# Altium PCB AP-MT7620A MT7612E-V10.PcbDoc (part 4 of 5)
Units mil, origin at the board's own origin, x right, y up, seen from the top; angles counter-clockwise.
Board outline 4645.67 x 3740.16 mil, 4 copper layers (Top, Inner Layer 2, Inner Layer 3, Bottom), stack 35.4 mil thick; 603 components, 409 nets, 1850 pads, 2004 vias.
Unrouted connection lines stored in the file: 90.
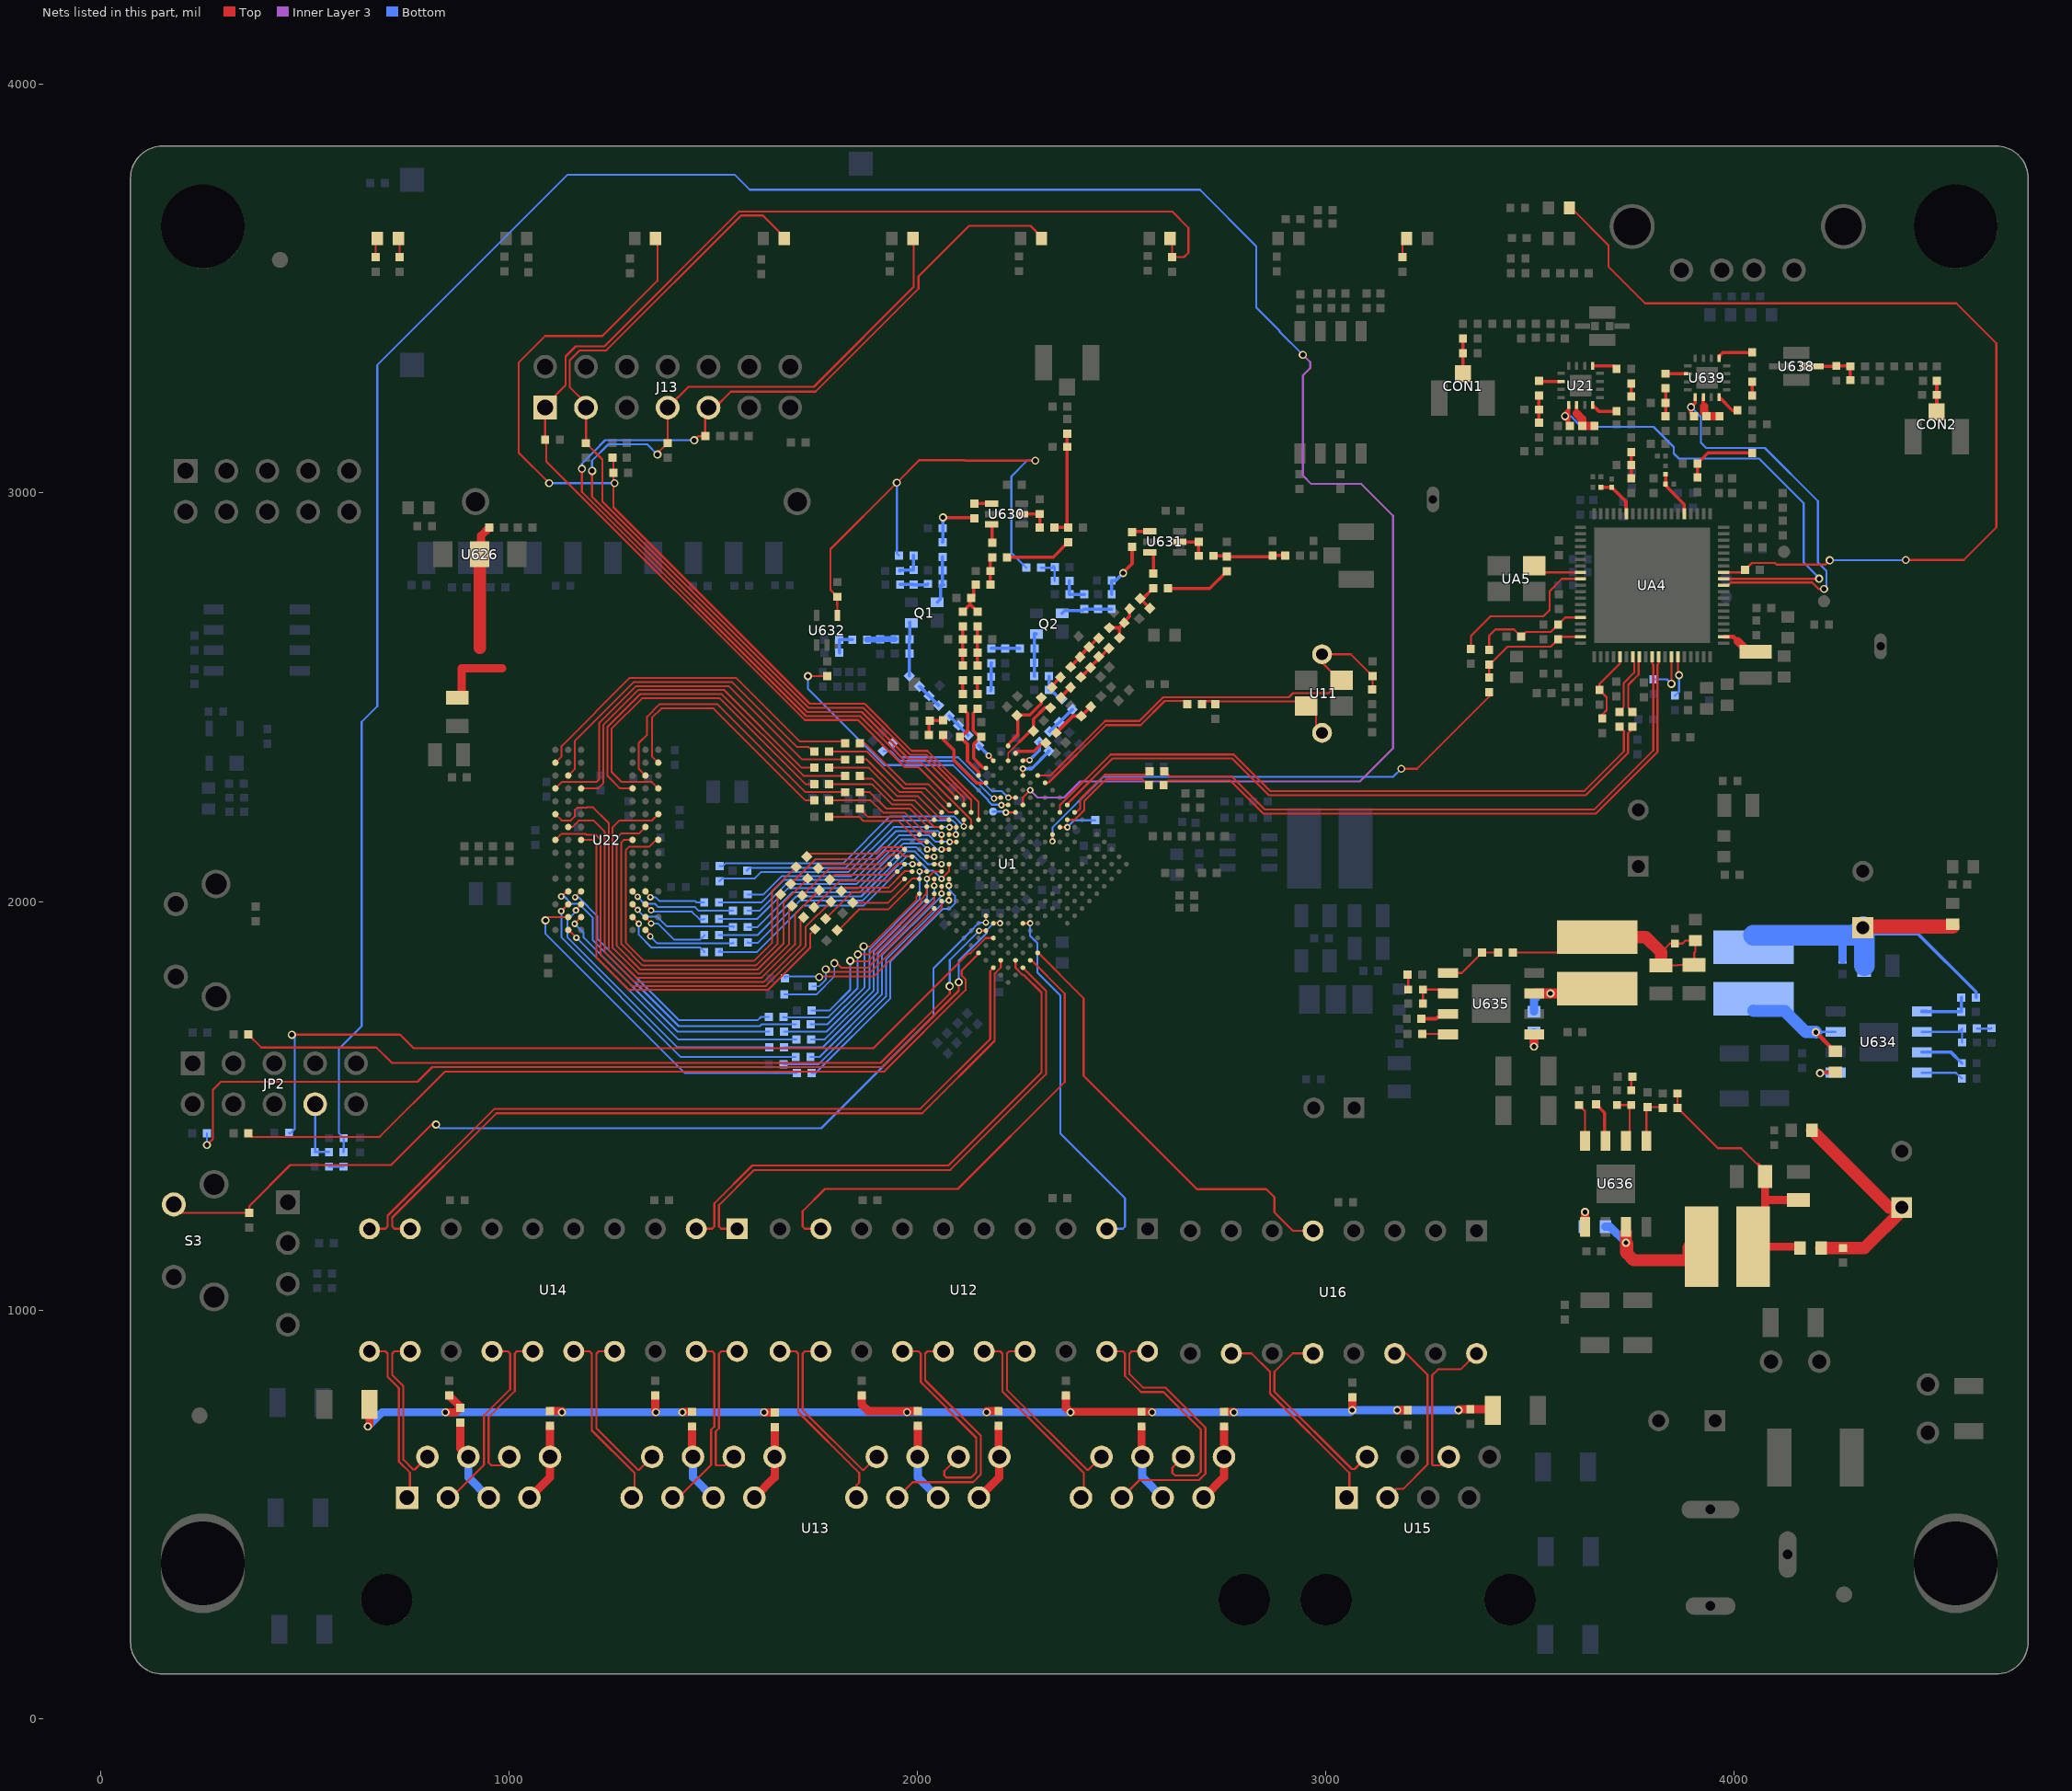
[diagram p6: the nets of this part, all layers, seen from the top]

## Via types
v1: diameter 20, hole 12, Top to Bottom, 1824 vias
v2: diameter 16, hole 8, Top to Bottom, 180 vias

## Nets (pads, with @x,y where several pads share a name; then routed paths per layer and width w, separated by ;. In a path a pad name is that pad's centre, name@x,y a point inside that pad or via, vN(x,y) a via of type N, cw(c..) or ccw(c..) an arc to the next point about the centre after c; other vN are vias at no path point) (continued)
LANP0_C1: R120.1 U13.4 U13.5 | length 213
  Top w20: R120.1@881,725 881,661 U13.4@901,641
  Bottom w20: U13.4@901,641 901,591 U13.5@951,541
LANP0_C2: R119.1 U13.7 U13.8 | length 196.7
  Top w20: U13.7@1051,541 1101,591 U13.8@1101,641 R119.1@1101,717
LANP1_C1: R117.1 U13.12 U13.13 | length 196.7
  Top w20: R117.1@1449,715 1449,641 U13.12@1451,641
  Bottom w20: U13.12@1451,641 1451,591 U13.13@1501,541
LANP1_C2: R116.1 U13.15 U13.16 | length 192.7
  Top w20: U13.15@1601,541 1651,591 U13.16@1651,641 R116.1@1651,713
LANP2_C1: R114.1 U13.20 U13.21 | length 196.7
  Top w20: U13.20@2001,641 R114.1@2001,717
  Bottom w20: U13.20@2001,641 2001,591 U13.21@2051,541
LANP2_C2: R113.1 U13.23 U13.24 | length 198.7
  Top w20: U13.23@2151,541 2201,591 U13.24@2201,641 2199,641 R113.1@2199,717
LANP3_C1: R111.1 U13.28 U13.29 | length 196.7
  Top w20: R111.1@2549,715 2549,641 U13.28@2551,641
  Bottom w20: U13.28@2551,641 2551,591 U13.29@2601,541
LANP3_C2: R110.1 U13.31 U13.32 | length 194.7
  Top w20: U13.31@2701,541 2751,591 U13.32@2751,641 R110.1@2751,715
LED_7612_5G: D17.2 RA10.2 UA4.50 | length 2380.6
  Top w5: D17.2@3596.59,3698 3600.53,3698 3692,3606.53 3692,3554 3782,3464 4544,3464 4642,3366 4642,2916 4562,2836 v1(4420,2836) ; UA4.50@3974.2,2805.5 4020.38,2805.5 RA10.2@4026.88,2812 4043.38,2828.5 4099.76,2828.5 4103.76,2824.5 4223.4,2824.5 v1(4233.99,2835.09)
  Bottom w5: v1(4233.99,2835.09) 4419.09,2835.09 v1(4420,2836)
LINK0: C845.1 D12.2 R478.2 U1.H4 | length 2376.8
  Top w5: v1(1099,3024) 1024,3099 1024,3319 1089,3384 1229,3384 1364,3519 1364,3618.37 1363.37,3619 D12.2@1363.37,3622.78 ; R478.2@1254,3086 1256,3086 C845.1@1256,3049 v1@1256,3027 ; v1(1259,3024) v1@1256,3027 ; U1.H4@2150.12,2200.07 2150.12,2243.61 2024.73,2369 1986.5,2369 1871.5,2484 1736.69,2484 1256,2964.69 v1@1256,3027
  Bottom w5: v1(1099,3024) v1(1259,3024)
LINK1: D11.2 J13.3 R476.2 U1.H3 | length 2314.1
  Top w5: D11.2@1678.33,3622.78 1622.11,3679 1569,3679 1239,3349 1174,3349 1149,3324 1149,3259.04 1189,3219.04 J13.3@1189,3209 R476.2@1189,3122 1229,3082 1229,2978.92 1733.92,2474 1868,2474 1983,2359 2022,2359 2132.02,2248.98 U1.H3@2132.02,2218.17
LINK2: D10.2 J13.7 R474.2 U1.H2 | length 2481.2
  Top w5: v1(1204,3054) 1204,2990.84 1730.84,2464 1864,2464 1979,2349 2019,2349 2113.93,2254.07 U1.H2@2113.93,2236.26 ; v1(1364,3094) 1364,3097 R474.2@1389,3122 J13.7@1389,3209 1440,3260 1747,3260 1991,3504 1991,3620.49 1993.29,3622.78 D10.2@1989.35,3622.78
  Bottom w5: v1(1204,3054) 1204,3079 1244,3119 1339,3119 v1(1364,3094)
LINK3: D9.2 J13.9 R473.2 U1.H1 | length 2738.6
  Top w5: v1(1179,3059) 1179,3002.72 1727.72,2454 1860,2454 1975,2339 2011.19,2339 U1.H1@2095.83,2254.36 ; v1(1454,3129) 1464,3139 R473.2@1481,3139 1481,3204 1484,3204 J13.9@1489,3209 1505,3209 1544,3248 1751,3248 2003,3500 2003,3530 2127,3654 2277.03,3654 2308.25,3622.78 D9.2@2304.31,3622.78
  Bottom w5: v1(1179,3059) 1179,3071 1236,3129 v1(1454,3129)
LINK4: C846.1 D8.2 J13.1 R477.2 U1.J4 | length 3544.5
  Top w5: U1.J4@2132.02,2181.98 2132.02,2200 2003.02,2329 1970,2329 1855,2444 1724.98,2444 1092,3076.98 1092,3127 R477.2@1089,3130 J13.1@1089,3209 1093.55,3213.55 1093.55,3218.55 1139,3264 1139,3334 1164,3359 1234,3359 1564,3689 2624,3689 2664,3649 2664,3588 2653,3577 C846.1@2624,3577 2624,3622 2623.22,3622.78 D8.2@2619.28,3622.78
LNA2G5G_PE0: C160.2 U21.5 UA4.49 | length 1210.9
  Top w5: UA4.49@3974.2,2789.75 3974.2,2790 v1(4208,2790)
  Top w8: U21.5@3594.47,3215.26 3594.47,3204 ; C160.2@3598,3164 3594.47,3164 3594.47,3176 ; 3594.47,3176 3594.47,3204 ; 3594.47,3176 3591.16,3176 3586,3181.16 v1(3586,3188) 3586,3195.53 3594.47,3204
  Bottom w5: v1(3586,3188) 3600,3188 3626,3162 3802.45,3162 3852,3112.45 3852,3096.59 3864.59,3084 4061,3084 4170,2975 4170,2830 4210,2790 v1(4208,2790)
LNA2G5G_PE1: C162.2 U639.5 UA4.48 | length 977.7
  Top w5: UA4.48@3974.2,2774 3986,2774 3992.75,2780.75 4190.76,2780.75 4206.51,2765 v1(4220,2765)
  Top w8: v1(3894.42,3210.04) 3904.47,3220.09 U639.5@3904.47,3234.26
  Top w10: v1(3894.42,3210.04) 3894.42,3196.52 3902,3188.94 C162.2@3902,3188
  Bottom w5: v1(3894.42,3210.04) 3918.5,3185.96 3918.5,3122.87 3931.51,3109.87 4075.13,3109.87 4205,2980 4205,2830 4226,2809 4226,2771 v1(4220,2765)
LNA_PE_G0: R918.2 R928.2 R954.2 U632.4 | length 1254.4
  Top w5: U632.4@1804.59,2700.28 1804.59,2724.73 1804,2725.32 R954.2@1804,2746 1787.5,2762.5 1787.5,2862.5 v1(1950,3025) 2005,3080 2115.25,3080 2116.25,3079 v1(2289,3079)
  Bottom w5: v1(1950,3025) 1950,2852 R918.2@1955,2847 ; R928.2@2267,2817 2230.5,2853.5 2230.5,3040.5 2269,3079 v1(2289,3079)
LNA_RX0_IN: C996.1 C1002.1 C1006.2 | length 142.3
  Top w8: v1(2504,2804) 2504,2805 2526,2827 C1006.2@2526,2868
  Bottom w8: C1002.1@2476,2752 C996.1@2476,2785.5 2485.5,2785.5 v1(2504,2804)
LNA_RX1_IN: C984.1 C989.1 C1053.1 | length 138.2
  Top w8: v1(2063,2940) 2137.5,2940 C1053.1@2139.5,2938
  Bottom w8: C984.1@2062,2879.5 2062.5,2880 C989.1@2062.5,2913.5 2063,2914 v1(2063,2940)
LNA_V0: C1001.2 L641.1 R924.1 | length 69.7
  Bottom w8: R924.1@2181.5,2619.5 C1001.2@2215,2619.5 2250.5,2619.5 L641.1@2251,2619
LNAO0: C1003.2 C1005.2 L641.2 Q2.3 | length 110.2
  Bottom w8: C1003.2@2286.5,2551.5 C1005.2@2286.5,2584 2287,2584 L641.2@2287,2619 2287,2656 2289.91,2656 Q2.3@2291.5,2654.41
LNAO1: C980.2 C982.2 L638.2 Q1.3 | length 133.3
  Bottom w8: C980.2@1980.27,2552.23 1980.27,2606.27 C982.2@1981,2607 L638.2@1981,2642 1981.78,2642.78 1981.78,2683.8 Q1.3@1981,2683.03
MA0: R65.1 U1.L4 | length 656.6
  Top w5: v2(2079.5,2146) 2079.71,2145.79 U1.L4@2095.83,2145.79
  Bottom w4.5: R65.1@1514.5,1997.5 1618.5,1997.5 1673.5,2052.5 1845.5,2052.5 1955.5,2162.5 2028.5,2162.5 2045,2146 v2(2079.5,2146)
MA0+: U13.1 U14.11 | length 424.7
  Top w5: U14.11@659,899 698,899 703.5,893.5 703.5,836.72 731,809.22 731,629.22 757.97,602.25 757.97,547.97 U13.1@751,541
MA0-: U13.2 U14.12 | length 399.6
  Top w5: U14.12@759,899 720,899 714.5,893.5 714.5,841.28 742,813.78 742,633.78 765.75,610.03 770.03,610.03 U13.2@801,641
MA1: R67.1 U1.T5 | length 548.5
  Top w4.5: v1(1854.5,1870.5) 1881,1870.5 2009.5,1999 2009.5,2005.5 2022.5,2018.5 2022.5,2036.26 U1.T5@2023.45,2037.21
  Bottom w4.5: R67.1@1672.5,1717.5 1671.5,1717.5 1672.5,1716.5 1782.5,1716.5 1854.5,1788.5 v1(1854.5,1870.5)
MA1+: U13.9 U14.16 | length 445.4
  Top w5: U14.16@1159,899 1198,899 1203.5,893.5 1203.5,705.72 1307.97,601.25 1307.97,555.97 1301,549 U13.9@1301,541
MA1-: U13.10 U14.17 | length 421.7
  Top w5: U14.17@1259,899 1220,899 1214.5,893.5 1214.5,710.28 1315.75,609.03 1319.03,609.03 U13.10@1351,641
MA2: R69.1 U1.M4 | length 576.2
  Top w5: v2(2059.5,2127.5) 2059.69,2127.69 U1.M4@2077.74,2127.69
  Bottom w4.5: R69.1@1584.5,1977.5 1613.5,1977.5 1678.5,2042.5 1851.1,2042.5 1961.1,2152.5 2023.5,2152.5 2048.5,2127.5 v2(2059.5,2127.5)
MA2+: U12.11 U13.17 | length 464.1
  Top w5: U12.11@1664,899 1703,899 1708.5,893.5 1708.5,750.72 1857.97,601.25 1857.97,578.03 1851,571.06 U13.17@1851,541
MA2-: U12.12 U13.18 | length 440.3
  Top w5: U12.12@1764,899 1725,899 1719.5,893.5 1719.5,755.28 1865.75,609.03 1869.03,609.03 U13.18@1901,641
MA3: R71.1 U1.R6 | length 563.6
  Top w4.5: v2(2059.5,2019.5) 2059.64,2019.64 U1.R6@2059.64,2037.21
  Bottom w4.5: R71.1@1738.5,1619.5 1760.5,1619.5 1913.5,1772.5 1913.5,1867.5 2059.5,2013.5 v2(2059.5,2019.5)
MA3+: U12.16 U13.25 | length 484.8
  Top w5: U12.16@2164,899 2203,899 2208.5,893.5 2208.5,800.72 2407.97,601.25 2407.97,547.97 U13.25@2401,541
MA3-: U12.17 U13.26 | length 461
  Top w5: U12.17@2264,899 2225,899 2219.5,893.5 2219.5,805.28 2415.75,609.03 2419.03,609.03 U13.26@2451,641
MA4: R73.1 U1.N3 | length 610
  Top w5: v2(2024.5,2127.5) 2024.69,2127.69 U1.N3@2041.55,2127.69
  Bottom w4.5: R73.1@1514.5,1957.5 1608.5,1957.5 1683.5,2032.5 1855.5,2032.5 1965.5,2142.5 2009.5,2142.5 v2(2024.5,2127.5)
MA4+: U15.1 U16.10 | length 504.5
  Top w5: U16.10@2769,894 2818.41,894 2863.5,848.91 2863.5,795.72 3057.97,601.25 3057.97,547.97 U15.1@3051,541
MA4-: U15.2 U16.12 | length 479.3
  Top w5: U16.12@2969,894 2919.59,894 2874.5,848.91 2874.5,800.28 3063.98,610.8 3070.8,610.8 U15.2@3101,641
MA5: R75.1 U1.R5 | length 620.5
  Top w4.5: v2(2041.5,2038.5) v2(2041.5,2038.5) U1.R5@2041.55,2055.31
  Bottom w4.5: R75.1@1673.5,1643.5 1769.5,1643.5 1903.5,1777.5 1903.5,1872.5 2041.5,2010.5 v2(2041.5,2038.5)
MA6: R77.1 U1.P3 | length 565.4
  Top w5: U1.P3@2023.45,2109.6 2041.4,2109.6 v2(2041.5,2109.5)
  Bottom w4.5: R77.1@1584.5,1937.5 1608.76,1937.5 1693.76,2022.5 1859.5,2022.5 1969.5,2132.5 1998.5,2132.5 2021.5,2109.5 v2(2041.5,2109.5)
MA7: R79.1 U1.P6 | length 641.7
  Top w4.5: v2(2077.5,2039) 2077.74,2039.24 U1.P6@2077.74,2055.31
  Bottom w4.5: R79.1@1741.5,1580.5 1751.5,1580.5 1933.5,1762.5 1933.5,1852.5 2063.5,1982.5 2079.5,1982.5 2092.5,1995.5 2092.5,2014.5 2077.5,2029.5 v2(2077.5,2039)
MA8: R81.1 U1.P4 | length 660.7
  Top w5: U1.P4@2041.55,2091.5 v2(2059.5,2091.5)
  Bottom w4.5: R81.1@1514.5,1917.5 1608.5,1917.5 1703.5,2012.5 1863,2012.5 1973,2122.5 1994.5,2122.5 2025.5,2091.5 v2(2059.5,2091.5)
MA9: R83.1 U1.R4 | length 608.1
  Top w4.5: v2(2005.5,2073.5) 2005.6,2073.4 U1.R4@2023.45,2073.4
  Bottom w4.5: R83.1@1673.5,1681.5 1777.5,1681.5 1883.5,1787.5 1883.5,1882.5 2005.5,2005.5 v2(2005.5,2073.5)
MA10: R85.1 U1.U5 | length 466
  Top w4.5: v1(1869,1890) 1885,1890 1997.62,2002.62 1997.62,2011.38 U1.U5@2005.36,2019.12
  Bottom w4.5: R85.1@1739.5,1699.5 1780.5,1699.5 1871,1790 1871,1890 v1(1869,1890)
MA11: R87.1 U1.R3 | length 589.5
  Top w5: v2(1988.5,2091.5) U1.R3@2005.36,2091.5
  Bottom w4.5: R87.1@1514.5,1876.5 1513.5,1876.5 1518.5,1881.5 1518.5,1876.5 1607.5,1876.5 1721.25,1990.25 1868.75,1990.25 1970.65,2092.15 1987.85,2092.15 v2(1988.5,2091.5)
MA12: R89.1 U1.P5 | length 572.8
  Top w4.5: v2(2023.5,2055.5) 2041.4,2073.4 U1.P5@2059.64,2073.4
  Bottom w4.5: R89.1@1740.5,1662.5 1773.5,1662.5 1893.5,1782.5 1893.5,1877.5 2023.5,2008.5 v2(2023.5,2055.5)
MA13: R826.1 U1.N5 | length 630.7
  Top w4.5: v2(2059.5,2055.5) 2077.5,2073.5 2077.5,2091.26 U1.N5@2077.74,2091.5
  Bottom w4.5: R826.1@1585.5,1899.5 1584.5,1899.5 1584.5,1898.5 1609.5,1898.5 1713.5,2002.5 1866.5,2002.5 1974,2110 1993,2110 2027.5,2075.5 2039.5,2075.5 v2(2059.5,2055.5)
MADDR0: R65.2 U22.M8 | length 157.2
  Top w4: U22.M8@1334.54,2024.83 1334.06,2024.35 1347.42,2010.99 v2(1346.93,2010.5)
  Bottom w4.5: v2(1346.93,2010.5) 1359.62,2010.5 1368.62,2001.5 1456,2001.5 1460,1997.5 R65.2@1478.5,1997.5
MADDR1: R67.2 U22.M3 | length 654.5
  Top w4.5: v2(1162.6,2010.4) 1175.6,2024.83 U22.M3@1177.06,2024.83
  Bottom w4.5: v2(1162.6,2010.4) 1170.6,2010.4 1216.4,1964.6 1216.4,1909.6 1416,1710 1610,1710 1617.5,1717.5 R67.2@1636.5,1717.5
MADDR2: R69.2 U22.M7 | length 265.6
  Top w4: U22.M7@1303.05,2024.83 1303.05,2023.95 v2(1315.5,2011.5)
  Bottom w4.5: v2(1315.5,2011.5) 1332.5,1994.5 1358.13,1994.5 1366.13,1986.5 1456.5,1986.5 1465.5,1977.5 R69.2@1548.5,1977.5
MADDR3: R71.2 U22.N2 | length 783.3
  Top w4.5: v2(1128.5,1976.5) U22.N2@1145.57,1993.34
  Bottom w4.5: v2(1128.5,1976.5) 1128.5,1912.5 1421.5,1619.5 R71.2@1702.5,1619.5
MADDR4: R73.2 U22.N8 | length 160.8
  Top w4.5: U22.N8@1334.54,1993.34 1345.5,1982.38 1345.5,1981.5 v2(1348.5,1978.5)
  Bottom w4.5: v2(1348.5,1978.5) 1353.5,1975 1448.5,1975 1467,1956.5 1478,1956.5 1479,1957.5 R73.2@1479.5,1957.5
MADDR5: R75.2 U22.N3 | length 701.6
  Top w4.5: v2(1164.5,1978.5) 1163.5,1979.5 1163.5,1979.78 U22.N3@1177.06,1993.34
  Bottom w4.5: v2(1164.5,1978.5) 1164.5,1976 1144,1955.5 1144,1912 1412.5,1643.5 R75.2@1637.5,1643.5 R75.2@1638.5,1643.5
MADDR6: R77.2 U22.N7 | length 274.4
  Top w4.5: U22.N7@1303.05,1993.34 1315.5,1980.89 v2(1315.5,1979.5)
  Bottom w4.5: v2(1315.5,1979.5) 1332.5,1962.5 1363.29,1962.5 1386.29,1939.5 1551.5,1939.5 R77.2@1549.5,1937.5
MADDR7: R79.2 U22.P2 | length 848.3
  Top w4.5: v1(1089.99,1953.95) 1097.88,1961.84 U22.P2@1145.57,1961.84
  Bottom w4.5: v1(1089.99,1953.95) 1089.99,1921.01 1430.5,1580.5 R79.2@1705.5,1580.5
MADDR8: R81.2 U22.P8 | length 173.4
  Top w4.5: U22.P8@1334.54,1961.84 1334.2,1961.5 1348.85,1946.85 v2(1348.5,1946.5)
  Bottom w4.5: v2(1348.5,1946.5) 1365.19,1946.5 1404.69,1907 1469,1907 R81.2@1479.5,1917.5
MADDR9: R83.2 U22.P3 | length 615.2
  Top w4.5: v2(1161.5,1945.5) 1161.5,1946.28 U22.P3@1177.06,1961.84
  Bottom w4.5: v2(1161.5,1945.5) 1183.5,1923.5 1183.5,1911.5 1413.5,1681.5 R83.2@1637.5,1681.5
MADDR10: R85.2 U22.M2 | length 762.7
  Top w4.5: v2(1128.5,2012.5) 1128.5,2014.77 U22.M2@1145.57,2024.83
  Bottom w4.5: v2(1128.5,2012.5) 1135.8,2012.5 1153.5,1994.8 1171.2,1994.8 1205.8,1960.2 1205.8,1905.2 1416,1695 1615,1695 1619.5,1699.5 R85.2@1703.5,1699.5
MADDR11: R87.2 U22.P7 | length 229.5
  Top w4: U22.P7@1303.05,1961.84 1302.82,1961.62 1318.72,1945.72 v2(1318.5,1945.5)
  Bottom w4.5: v2(1318.5,1945.5) 1318.5,1918.5 1349.45,1887.55 1468.45,1887.55 1479.5,1876.5 R87.2@1478.5,1876.5
MADDR12: R89.2 U22.R2 | length 669.9
  Top w4.5: U22.R2@1145.57,1930.35 1146.65,1930.35 v2(1165.5,1911.5)
  Bottom w4.5: v2(1165.5,1911.5) 1414.5,1662.5 R89.2@1704.5,1662.5
MADDR13: R826.2 U22.R8 | length 232.7
  Top w4.5: U22.R8@1334.54,1930.35 1346.5,1918.39 v2(1346.5,1914.5)
  Bottom w4.5: v2(1346.5,1914.5) 1363.5,1897.5 1548.5,1897.5 R826.2@1550.5,1899.5
MB0+: U13.3 U14.14 | length 467.3
  Top w5: U13.3@851,541 859.23,541 939.5,621.27 939.5,742.28 1003.5,806.28 1003.5,893.5 998,899 U14.14@959,899
MB0-: U13.6 U14.15 | length 402.4
  Top w5: U13.6@1001,641 979.75,619.75 957.25,619.75 950.5,626.5 950.5,737.72 1014.5,801.72 1014.5,893.5 1020,899 U14.15@1059,899
MB1+: U13.11 U14.19 | length 450.2
  Top w5: U13.11@1401,541 1415.37,541 1495.5,621.13 1495.5,707.28 1503.5,715.28 1503.5,893.5 1498,899 U14.19@1459,899
MB1-: U13.14 U14.20 | length 376.3
  Top w5: U13.14@1551,641 1529.75,619.75 1507.88,619.75 1506.5,621.13 1506.5,702.72 1514.5,710.72 1514.5,893.5 1520,899 U14.20@1559,899
MB2+: U12.15 U13.19 | length 626.9
  Top w5: U13.19@1951,541 1989,579 2136.78,579 2155.5,597.72 2155.5,692.28 2019.5,828.28 2019.5,893.5 2025,899 U12.15@2064,899
MB2-: U12.14 U13.22 | length 540.5
  Top w5: U12.14@1964,899 2003,899 2008.5,893.5 2008.5,823.72 2144.5,687.72 2144.5,602.28 2132.22,590 2071,590 2066,595 2066,606 U13.22@2101,641
MB3+: U12.20 U13.27 | length 678.5
  Top w5: U13.27@2501,541 2544,584 2689.56,584 2705.5,599.94 2705.5,712.28 2607.28,810.5 2552.28,810.5 2519.5,843.28 2519.5,893.5 2525,899 U12.20@2564,899
MB3-: U12.19 U13.30 | length 572.1
  Top w5: U12.19@2464,899 2503,899 2508.5,893.5 2508.5,838.72 2547.72,799.5 2602.72,799.5 2694.5,707.72 2694.5,604.5 2685,595 2631,595 2624.56,601.44 2624.56,614.56 U13.30@2651,641
MB4+: U15.3 U16.14 | length 453.7
  Top w5: U15.3@3151,541 3172.25,562.25 3189.48,562.25 3249.5,622.28 3249.5,841.59 3197.09,894 U16.14@3169,894
MB4-: U15.6 U16.16 | length 399.7
  Top w5: U15.6@3301,641 3279.75,619.75 3262.85,619.75 3260.5,622.1 3260.5,840.5 3275,855 3330.39,855 U16.16@3369.39,894
MBA0: R97.1 U1.U6 | length 437.9
  Top w4.5: v1(1836,1855) 1836,1854 1880,1854 2021.5,1995.5 2021.5,1999.07 U1.U6@2023.45,2001.02
  Bottom w4.5: R97.1@1741.5,1733.5 1785.5,1733.5 1836,1784 v1(1836,1855)
MBA1: R98.1 U1.T6 | length 508.1
  Top w4.5: v1(1797,1849) 1803.29,1849 1814.29,1838 1879,1838 2041.5,2000.5 U1.T6@2041.55,2019.12 U1.T6@2041.55,2019.12
  Bottom w4: R98.1@1674.5,1772.5 1752.86,1772.5 1797,1816.64 v1(1797,1849)
MBA2: R827.1 U1.R7 | length 640.1
  Top w4.5: v2(2077.5,2003) 2077.74,2003.24 U1.R7@2077.74,2019.12
  Bottom w4.5: R827.1@1672.5,1601.5 1757.5,1601.5 1923.5,1767.5 1923.5,1857.5 2069.25,2002.75 2077.25,2002.75 v2(2077.5,2003)
MCAS_N: R104.1 U1.M3 | length 560.7
  Top w5: v2(2059.5,2163.5) 2059.64,2163.36 U1.M3@2059.64,2145.79
  Bottom w4.5: R104.1@1584.5,2017.5 1623.5,2017.5 1668.5,2062.5 1838.5,2062.5 1948.5,2172.5 2050.5,2172.5 v2(2059.5,2163.5)
MCKE: R101.1 U1.U7 | length 397.3
  Top w4.5: v1(1776,1834) 1782.5,1827.5 1886.12,1827.5 U1.U7@2041.55,1982.93
  Bottom w4: R101.1@1743.5,1792.5 1760.13,1792.5 1776,1808.37 v1(1776,1834)
MCS_N: R106.1 U1.K3 | length 635.9
  Top w5: v2(2079,2182) U1.K3@2095.83,2181.98
  Bottom w4.5: 1602.5,2056.5 1618.5,2072.5 1831.5,2072.5 1942,2182 v2(2079,2182)
  Bottom w5: R106.1@1516.5,2049.5 1515.5,2049.5 1522.5,2056.5 1602.5,2056.5
MD0: R64.2 U1.T1 | length 209.7
  Top w4.5: R64.2@1757.66,2081.8 1767.43,2091.57 1909.43,2091.57 1931.5,2113.63 1949.5,2113.63 1951.07,2112.06 U1.T1@1951.07,2109.6
MD1: R66.2 U1.U2 | length 242.5
  Top w4.5: R66.2@1747.06,1986.34 1746.35,1985.63 1746.35,1986.35 1810.3,2050.3 1925.97,2050.3 1949.07,2073.4 U1.U2@1951.07,2073.4
MD2: R68.2 U1.R2 | length 335.9
  Top w4.5: R68.2@1690.49,2042.91 1751.29,2103.71 1901.71,2103.71 1921.5,2123.5 1955.3,2123.5 1967.3,2111.5 1985.36,2111.5 U1.R2@1987.26,2109.6
MD3: R70.2 U1.U3 | length 234.7
  Top w4.5: R70.2@1775.34,1958.05 1840.64,2023.36 1935.83,2023.36 1968.48,2056 U1.U3@1969.17,2055.31
MD4: R72.2 U1.T3 | length 198.1
  Top w4.5: R72.2@1814.23,2025.23 1822.5,2033.5 1928.5,2033.5 1969.4,2074.4 U1.T3@1988.26,2074.4 ; U1.T3@1987.26,2073.4 U1.T3@1988.26,2074.4 ; U1.T3@1990.5,2074.4 U1.T3@1988.26,2074.4
MD5: R74.2 U1.R1 | length 251.7
  Top w4.5: R74.2@1729.38,2110.08 1736.5,2117.2 1900.7,2117.2 1916.8,2133.3 1963.56,2133.3 U1.R1@1969.17,2127.69
MD6: R76.2 U1.T2 | length 199.8
  Top w4.5: R76.2@1785.95,2053.51 1798.33,2065.9 1925.9,2065.9 1952.5,2092.5 1968.17,2092.5 U1.T2@1969.17,2091.5
MD7: R78.2 U1.U1 | length 247.3
  Top w4.5: R78.2@1718.77,2014.62 1784.08,2079.92 1915.5,2079.92 1928.58,2093 1931.48,2093 U1.U1@1932.98,2091.5
MD8: R80.2 U1.M1 | length 201.5
  Top w4.5: R80.2@1859.5,2267.5 1884,2267.5 1924,2227.5 1981.5,2227.5 2023.45,2185.55 U1.M1@2023.45,2181.98
MD9: R82.2 U1.J2 | length 373.2
  Top w4.5: R82.2@1784.5,2367.5 1876.5,2367.5 1966.5,2277.5 2018.5,2277.5 2077.83,2218.17 U1.J2@2095.83,2218.17
MD10: R84.2 U1.L1 | length 230.6
  Top w4.5: R84.2@1859.5,2307.5 1863.5,2307.5 1863.5,2300.5 1890.31,2300.5 1943.31,2247.5 1994.12,2247.5 U1.L1@2041.55,2200.07
MD11: R86.2 U1.K2 | length 346
  Top w4.5: R86.2@1784.5,2327.5 1881.8,2327.5 1951.8,2257.5 2002.1,2257.5 2057.1,2202.5 2075.31,2202.5 U1.K2@2077.74,2200.07
MD12: R88.2 U1.K1 | length 253.7
  Top w4.5: R88.2@1859.5,2347.5 1876.5,2347.5 1956.5,2267.5 2010.31,2267.5 U1.K1@2059.64,2218.17
MD13: R90.2 U1.L2 | length 318.9
  Top w4.5: R90.2@1784.5,2287.5 1888.7,2287.5 1938.7,2237.5 1985.9,2237.5 2040.9,2182.5 2059.12,2182.5 U1.L2@2059.64,2181.98
MD14: R91.2 U1.J1 | length 280.9
  Top w4.5: R91.2@1859.5,2387.5 1871.5,2387.5 1971.5,2287.5 2026.5,2287.5 U1.J1@2077.74,2236.26
MD15: R92.2 U1.M2 | length 291.7
  Top w4.5: R92.2@1784.5,2247.5 1886.5,2247.5 1916.5,2217.5 1969.7,2217.5 2019.7,2167.5 2037.93,2167.5 U1.M2@2041.55,2163.88
MDATA0: R64.1 U22.G8 | length 988.8
  Top w4.5: U22.G8@1334.54,2182.31 1318.43,2166.2 1275.2,2166.2 1264.5,2155.5 1264.5,1891.5 1322.5,1833.5 1609.5,1833.5 1672.5,1896.5 1672.5,1996.63 R64.1@1732.91,2057.05
MDATA1: R66.1 U22.G2 | length 1020.2
  Top w4.5: U22.G2@1145.57,2182.31 1155.5,2182.31 1171.19,2198 1208,2198 1234.5,2171.5 1234.5,1876.5 1307.5,1803.5 1624.5,1803.5 1714.5,1893.5 1714.5,1953.78 R66.1@1721.6,1960.88 R66.1@1722.31,1961.59
MDATA2: R68.1 U22.H7 | length 829.9
  Top w4.5: U22.H7@1303.05,2150.82 1281.5,2150.82 1275.5,2144.82 1275.5,1895.5 1327.5,1843.5 1604.5,1843.5 1658.5,1897.5 1658.5,2010.92 R68.1@1665.03,2017.45 R68.1@1665.74,2018.16
MDATA3: R70.1 U22.H3 | length 970.3
  Top w4.5: U22.H3@1177.06,2150.82 1205.18,2150.82 1214.5,2141.5 1214.5,1863.5 1294.5,1783.5 1634.5,1783.5 1738.5,1887.5 1738.5,1921.21 R70.1@1749.89,1932.6 R70.1@1750.59,1933.3
MDATA4: R72.1 U22.H1 | length 1113.9
  Top w4.5: U22.H1@1114.07,2150.82 1129.25,2166 1187.5,2166 1190,2163.5 1212.5,2163.5 1224.5,2151.5 1224.5,1870.5 1301.5,1793.5 1629.5,1793.5 1726.5,1890.5 1726.5,1937.5 R72.1@1788.77,1999.77 R72.1@1789.48,2000.48
MDATA5: R74.1 U22.H9 | length 922.6
  Top w4.5: U22.H9@1366.04,2150.82 1360.82,2150.82 1344.5,2134.5 1295.5,2134.5 1286.5,2125.5 1286.5,1899.5 1331.5,1854.5 1600.5,1854.5 1644.5,1898.5 1644.5,2025.2 R74.1@1703.92,2084.63 R74.1@1704.63,2085.33
MDATA6: R76.1 U22.F1 | length 1162.6
  Top w4.5: U22.F1@1114.07,2213.81 1129.38,2198.5 1152.5,2198.5 1161.5,2207.5 1161.5,2223.5 1167.5,2229.5 1191.2,2229.5 1192.5,2230.8 1206.3,2230.8 1244.5,2192.6 1244.5,1881.5 1312.5,1813.5 1619.5,1813.5 1700.5,1894.5 1700.5,1968.07 R76.1@1760.49,2028.06
MDATA7: R78.1 U22.F9 | length 1005.3
  Top w4.5: U22.F9@1366.04,2213.81 1350.73,2198.5 1271.5,2198.5 1254.5,2181.5 1254.5,1886.5 1317.5,1823.5 1614.5,1823.5 1686.5,1895.5 1686.5,1982.35 R78.1@1693.32,1989.17 R78.1@1694.02,1989.87
MDATA8: R80.1 U22.C8 | length 745.6
  Top w4.5: U22.C8@1334.54,2308.3 1318.5,2324.34 1318.5,2388.5 1338.5,2408.5 1338.5,2452.5 1368.5,2482.5 1511.5,2482.5 1726.5,2267.5 R80.1@1823.5,2267.5
MDATA9: R82.1 U22.C2 | length 809.3
  Top w4.5: U22.C2@1145.57,2308.3 1161.5,2324.23 1161.5,2392.5 1306.5,2537.5 1546.5,2537.5 1706,2378 1734.5,2378 1745,2367.5 R82.1@1748.5,2367.5 R82.1@1749.5,2367.5
MDATA10: R84.1 U22.D7 | length 893.2
  Top w4.5: U22.D7@1303.05,2276.8 1272.2,2276.8 1241.5,2307.5 1241.5,2427.5 1321.5,2507.5 1521.5,2507.5 1721.5,2307.5 R84.1@1823.5,2307.5 R84.1@1824.5,2307.5
MDATA11: R86.1 U22.D3 | length 834.4
  Top w4.5: U22.D3@1177.06,2276.8 1218.5,2276.8 1231.5,2289.8 1231.5,2432.5 1316.5,2517.5 1527.5,2517.5 1717.5,2327.5 R86.1@1748.5,2327.5 R86.1@1749.5,2327.5
MDATA12: R88.1 U22.D1 | length 969.7
  Top w4.5: U22.D1@1114.07,2276.8 1129.77,2292.5 1214.5,2292.5 1221.5,2299.5 1221.5,2437.5 1311.5,2527.5 1538.5,2527.5 1718.5,2347.5 R88.1@1823.5,2347.5 R88.1@1824.5,2347.5
MDATA13: R90.1 U22.D9 | length 852.4
  Top w4.5: U22.D9@1366.04,2276.8 1350.34,2292.5 1276.5,2292.5 1251.5,2317.5 1251.5,2422.5 1326.5,2497.5 1516.5,2497.5 1726.5,2287.5 R90.1@1748.5,2287.5 R90.1@1749.5,2287.5
MDATA14: R91.1 U22.B1 | length 878.5
  Top w4.5: U22.B1@1114.07,2339.8 1129.5,2355.22 1129.5,2380.5 1296.5,2547.5 1556.5,2547.5 1712.5,2391.5 1820.5,2391.5 1824.5,2387.5 R91.1@1823.5,2387.5
MDATA15: R92.1 U22.B9 | length 617.9
  Top w4.5: U22.B9@1366.04,2339.8 1350.5,2355.33 1350.5,2449.5 1373.5,2472.5 1501.5,2472.5 1726.5,2247.5 R92.1@1748.5,2247.5 R92.1@1749.5,2247.5
MDQM0: R95.1 U1.U4 | length 230.1
  Top w4.5: R95.1@1803.62,1929.77 1802.92,1929.06 1806.06,1929.06 1858.5,1981.5 1929.55,1981.5 1985.05,2037 1987.05,2037 U1.U4@1987.26,2037.21
MDQM1: R96.1 U1.N2 | length 264.5
  Top w4.5: R96.1@1784.5,2207.5 1857.5,2207.5 1867.5,2197.5 1953.5,2197.5 2004.21,2146.79 2022.45,2146.79 U1.N2@2023.45,2145.79
MDQS0: R93.1 U1.T4 | length 189.8
  Top w4.5: R93.1@1842.52,1996.94 1841.81,1996.24 1927.74,1996.24 1987.81,2056.31 2004.36,2056.31 U1.T4@2005.36,2055.31
MDQS1: R94.1 U1.N1 | length 174.2
  Top w4.5: R94.1@1859.5,2227.5 1858.5,2227.5 1878.5,2207.5 1961.74,2207.5 U1.N1@2005.36,2163.88
MODT: R479.1 U1.J3 | length 674.3
  Top w5: U1.J3@2113.93,2200.07 2113.93,2184.07 v2(2114,2184)
  Bottom w4.5: R479.1@1516.5,2086.5 1524,2086.5 1530.5,2093 1818,2093 1933.5,2208.5 2089.5,2208.5 v2(2114,2184)
MRAS_N: R103.1 U1.L3 | length 610.6
  Top w5: U1.L3@2077.74,2163.88 2094.38,2163.88 v2(2094.5,2164)
  Bottom w4.5: 1668.5,2082.5 1825.5,2082.5 1941.5,2198.5 2086.5,2198.5 2094.5,2190.5 v2(2094.5,2164)
  Bottom w5: R103.1@1583.5,2075.5 1582.5,2075.5 1589.5,2082.5 1668.5,2082.5
MWE_N: R105.1 U1.T7 | length 480.7
  Top w4.5: v1(1760,1815) 1761.5,1816.5 1892.5,1816.5 2060.5,1984.5 2060.5,2000.17 U1.T7@2059.64,2001.02
  Bottom w4: R105.1@1676.5,1812.5 1675.5,1812.5 1675.5,1816.5 1761.5,1816.5 v1(1760,1815)
N16872712: D13.1 R372.1 | length 64.4
  Top w5: R372.1@3188,3577 3188,3628.86 3194.08,3622.78 D13.1@3198.02,3622.78
N16996557: R894.1 R900.1 U626.2 | length 488
  Top w20: R900.1@874,2498.45 885,2498.45 885,2570.61 983.96,2570.61 ; U626.2@929,2849.98 932,2849.98 932,2895 R894.1@952,2915
  Top w30: U626.2@929,2849.98 929,2729 929.08,2728.92 929.08,2620.42
N17231224: C981.1 C983.2 C987.1 | length 66.3
  Bottom w8: C981.1@2078.23,2454.23 C987.1@2101.23,2431.23 2101.23,2430.77 C983.2@2124.77,2407.23
N17346690: C1020.1 C1021.1 C1022.1 L642.2 R895.1 R941.1 | length 1028.8
  Top w20: R895.1@4535,1939 R895.1@4535,1944.41
  Top w35: C1021.1@4315,1936.1 4316,1939 R895.1@4535,1939
  Bottom w8: C1021.1@4297.69,1920.69 4318.55,1920.69 4450,1920.69 4592,1778.69 R941.1@4592,1765
  Bottom w20: C1022.1@4265,1858 4265,1917.52
  Bottom w50: L642.2@4047,1917.52 4265,1917.52 4294.52,1917.52 4297.69,1920.69 4316,1939 4318.55,1936.45 4318.55,1920.69 C1020.1@4318.55,1843
N17346710: C1015.2 L642.1 U634.3 | length 291.6
  Top w10: v1(4200,1680) 4219.54,1660.46 4219.54,1660.06 4246,1633.59 C1015.2@4248,1633.59
  Bottom w5: v1(4200,1680) 4215,1680 4216,1681 U634.3@4248.39,1681
  Bottom w30: L642.1@4047,1732.48 4047.48,1732 4124,1732 4175,1681 4200,1681 v1(4200,1680)
N17346731: C1024.1 C1027.2 U634.6 | length 135.7
  Bottom w5: U634.6@4459.61,1681 4550,1681 C1024.1@4558,1689 C1027.2@4558,1655
N17346733: R941.2 R945.1 U634.5 | length 131.8
  Bottom w8: U634.5@4459.61,1731 4472.11,1731 4473.11,1730 R945.1@4556,1730 R941.2@4556,1765
N17346829: C1015.1 U634.1 | length 77.8
  Top w10: v1(4210,1580) 4212.41,1582.41 C1015.1@4248,1582.41
  Bottom w10: v1(4210,1580) 4211,1581 U634.1@4248.39,1581
N17346849: R940.2 U634.7 | length 108.9
  Bottom w8: U634.7@4459.61,1631 4531,1631 R940.2@4557.5,1604.5
N17346871: C1019.2 U634.8 | length 103.9
  Bottom w5: U634.8@4459.61,1581 4543,1581 C1019.2@4557.5,1566.5
N17346875: C1024.2 R943.1 | length 36.4
  Bottom w5: C1024.2@4594,1689 4629,1689 R943.1@4630,1690
N17402468: CA15.1 CON1.1 LA5.1 | length 86
  Top w8: CON1.1@3336,3292.04 CA15.1@3336,3342 LA5.1@3336,3378
N17402470: CA19.1 CON2.1 LA10.1 | length 76
  Top w8: CON2.1@4496,3198.04 CA19.1@4496,3240 LA10.1@4496,3274
N17424380: C929.1 C1045.1 L647.2 L648.1 | length 544.1
  Top w30: L648.1@4190.59,1440 4379.59,1251 4410,1251 4414,1247 4319,1152 C929.1@4266,1152 L647.2@4212.59,1152
N17424411: C1041.1 C1042.1 C1043.1 L646.2 L647.1 R949.1 | length 648.6
  Top w5: C1043.1@3861,1530 R949.1@3861,1495 3960,1396 4017,1396 4063,1350 4063,1355.07 4059.07,1359
  Top w20: C1042.1@4075.45,1327 4075.45,1269.55 ; L646.2@4075.52,1155 4075.45,1155.07 L646.2@4075.45,1155.25 ; C1041.1@4157,1269.55 4075.45,1269.55 ; L647.1@4161.41,1152 4158.16,1155.25 L646.2@4075.45,1155.25 ; L646.2@4075.45,1155.25 4075.45,1269.55
N17424413: C1036.2 L646.1 U636.3 | length 340.2
  Top w30: U636.3@3735,1190.89 v1(3735,1165) ; L646.1@3890.48,1155 3889,1153.52 3889,1122 3754,1122 3738,1138 ; v1(3735,1165) 3738,1162 3738,1138 ; v1(3735,1165) 3735,1141 3738,1138
  Bottom w20: C1036.2@3684.59,1204 3696,1204 v1(3735,1165)
N17424474: R949.2 R951.1 U636.5 | length 123.2
  Top w4.5: R949.2@3823,1497 R949.2@3825,1495
  Top w5: U636.5@3785,1414.61 3785,1497 R951.1@3788,1497 R949.2@3823,1497
N17424510: R948.2 U636.7 | length 100.1
  Top w8: R948.2@3662,1504 3683,1483 3683,1427.11 3685,1427.11 U636.7@3685,1414.61
N17424568: C1040.2 U636.8 | length 93.6
  Top w5: C1040.2@3620,1502 3635,1487 U636.8@3635,1414.61
N17424570: C1044.1 C1046.2 U636.6 | length 126.1
  Top w5: C1046.2@3713,1502 C1044.1@3744,1502 ; U636.6@3735,1414.61 3735,1427.11 3744,1436.11 C1044.1@3744,1502 ; C1044.1@3748,1502 C1044.1@3744,1502
N17424602: C1036.1 U636.1 | length 74.2
  Top w20: U636.1@3635,1203.39 v1(3635,1240)
  Bottom w20: C1036.1@3633.41,1204 3635,1204 v1(3635,1240)
N17424634: C1044.2 R950.1 | length 34.2
  Top w5: C1044.2@3748,1538 3748,1568 R950.1@3751,1571
N17424778: C1030.1 C1031.1 C1032.1 L643.2 L644.1 R944.1 | length 664.9
  Top w5: R944.1@3458,1875 3591.07,1875 3629.07,1912.99 L643.2@3665,1912.99 ; C1030.1@3821,1843.45 3861,1843.45 3862,1844.45 C1031.1@3902,1844.45 3902,1874.43 3905,1877.43 L644.1@3905,1904.41 3880.7,1904.41 3873.3,1897 C1032.1@3855,1897 3855,1896.95 3842.5,1896.95 3821,1875.45
  Top w30: L643.2@3665,1912.99 3783.46,1912.99 3821,1875.45 C1030.1@3821,1843.45
N17424780: C1023.2 L643.1 U635.3 | length 242
  Top w25: U635.3@3510.61,1775 v1(3550,1775) 3665,1775 L643.1@3665,1787.01
  Bottom w20: C1023.2@3510,1730.59 3510,1760 3525,1775 v1(3550,1775)
N17424846: R944.2 R947.1 U635.5 | length 143.3
  Top w5: U635.5@3299.39,1825 3333,1825 R947.1@3383,1875 R944.2@3422,1875
N17424874: R942.2 U635.7 | length 69.9
  Top w8: R942.2@3234.5,1713 3270,1713 3282,1725 U635.7@3299.39,1725
N17424932: C1029.2 U635.8 | length 64.4
  Top w5: C1029.2@3236,1676 3299.39,1676 U635.8@3299.39,1675
N17424934: C1034.1 C1035.2 U635.6 | length 99.8
  Top w5: C1035.2@3238,1750 C1034.1@3238,1784.5 3289.89,1784.5 U635.6@3299.39,1775
N17424966: C1023.1 U635.1 | length 65
  Top w20: v1(3510,1645) 3510,1675 U635.1@3510.61,1675
  Bottom w20: v1(3510,1645) C1023.1@3510,1679.41
N17424998: C1034.2 R946.1 | length 37.3
  Top w5: R946.1@3200,1821 3202,1819 C1034.2@3202,1784.5
N17536555: CA76.1 UA4.9 | length 385.9
  Top w5: CA76.1@3355,2618 3355.5,2618 3355.5,2650 3403.5,2698 3532.88,2698 3548,2713.12 3548,2759.61 3578.14,2789.75 UA4.9@3623.8,2789.75
N17551674: RA12.1 UA4.33 | length 100.2
  Top w5: UA4.33@3861.99,2598.8 3861.99,2556.88 v1(3864.97,2553.9)
  Bottom w5: RA12.1@3855,2504 3864.97,2513.97 v1(3864.97,2553.9)
N17552032: RA11.1 UA4.32 | length 113.7
  Top w5: v1(3846.2,2532.9) 3846.2,2577.71 3846.24,2577.75 UA4.32@3846.24,2598.8
  Bottom w5: RA11.1@3803,2544 3835.11,2544 v1(3846.2,2532.9)
N17624866: CA23.2 CA77.1 LA12.2 | length 64
  Top w8: CA77.1@3748,3036 LA12.2@3748,3068 CA23.2@3748,3100
N17700020: CA75.2 RA15.2 UA4.24 | length 183.2
  Top w5: CA75.2@3677,2448 3677,2457.62 3687.86,2468.48 3687.86,2500.08 RA15.2@3670.36,2517.58 3670.36,2532.62 3720.26,2582.52 UA4.24@3720.26,2598.8
N17723672: C977.2 L638.1 R913.1 | length 69
  Bottom w15: R913.1@1877,2641 1909,2641 C977.2@1909,2642 L638.1@1945,2642
N17723760: C979.2 L639.1 R914.2 | length 69
  Bottom w8: C979.2@1958,2776 1990.5,2776 R914.2@1991,2775.5 2024,2775.5 L639.1@2026,2777.5
N17723789: C978.2 R912.1 R913.2 | length 64
  Bottom w8: R912.1@1809,2609 C978.2@1809,2641 R913.2@1841,2641
N17732056: C980.1 C981.2 C986.1 | length 66.6
  Bottom w8: C980.1@2005.77,2526.77 C986.1@2029.27,2503.27 C981.2@2052.77,2479.73
N17758787: C993.1 C994.1 C998.2 | length 78.1
  Bottom w8: C998.2@2324.23,2415.73 C994.1@2342.5,2434 ; C994.1@2342.54,2434 C994.1@2347.27,2438.73 2348.18,2438.73 C993.1@2379.73,2470.27
N17758919: C999.2 L640.1 R922.2 | length 69.5
  Bottom w8: R922.2@2372.5,2785 C999.2@2372.5,2752 L640.1@2409,2752
N17841324: C1050.2 C1051.1 U631.5 | length 80.7
  Top w8: U631.5@2642.91,2880.5 2643.41,2880 C1051.1@2689,2880 2689.5,2879.5 2689,2879 C1050.2@2689,2846
N17849608: C1054.1 U630.3 | length 45
  Top w8: U630.3@2182.09,2922.91 2183.5,2921.5 C1054.1@2183.5,2878.5
N17851480: C1055.1 U631.3 | length 60.8
  Top w8: U631.3@2569.09,2854.91 2578,2854.91 C1055.1@2578,2803
N17873514: C1059.2 R919.1 | length 165.6
  Top w8: C1059.2@2219.5,2842.5 2219.4,2842.7 2219.7,2843 2333,2843 R919.1@2369.5,2879.5
N17876104: C1060.2 R921.1 | length 161.8
  Top w8: C1060.2@2614,2767 2615,2766 2716,2766 R921.1@2758,2808
N17877881: C1006.1 U631.1 | length 44
  Top w8: C1006.1@2526,2904 2528.09,2906.09 U631.1@2569.09,2906.09
N17881699: C988.1 R914.1 R918.1 | length 71.5
  Bottom w8: C988.1@1957.5,2809 1957.5,2811.5 R914.1@1991,2811.5 R918.1@1991,2847
N17897796: C993.2 C995.1 C1003.1 | length 75.1
  Bottom w8: C1003.1@2322.5,2551.5 C995.1@2322.5,2518 2327,2518 2350,2495 2353.54,2495 C993.2@2354.27,2495.73
N17903155: C1004.2 R923.1 R924.2 | length 68.1
  Bottom w8: R923.1@2179.5,2516.5 2181,2518 C1004.2@2181,2550 2181,2583.5 R924.2@2181.5,2583.5
N17910700: C997.1 R922.1 R928.1 | length 71.9
  Bottom w5: R928.1@2303,2817 C997.1@2336.5,2817 ; C997.1@2333,2822 C997.1@2336.5,2818.5 C997.1@2336.5,2817 ; R922.1@2336.5,2785 C997.1@2336.5,2817
N17924652: C1047.2 C1048.1 U630.5 | length 77.1
  Top w8: U630.5@2255.91,2948.5 C1048.1@2300,2948.5 C1047.2@2300,2915.5
N17949038: C78.2 L18.2 UA4.71 | length 105.7
  Top w8: C78.2@3674,3014 L18.2@3700,3014 3735,2979 3735,2963.81 3736.01,2962.8 UA4.71@3736.01,2949.2
N17949508: C79.2 L19.2 UA4.62 | length 118.6
  Top w8: C79.2@3832,3046 L19.2@3832,3022 3832,3020 3830,3020 3877.74,2972.26 UA4.62@3877.74,2949.2
N17950058: C171.2 U21.2 | length 54.7
  Top w8: C171.2@3522,3274 3523.16,3272.84 U21.2@3576.26,3272.84
N17950066: C170.2 R162.2 U21.6 | length 87.8
  Top w8: 3614.16,3194.73 U21.6@3614.16,3215.26 ; C170.2@3628.83,3164 C170.2@3628.83,3164.83
  Top w20: 3614.16,3194.73 3628,3180.89 C170.2@3628,3164 3628.83,3164 R162.2@3658,3164
N17950072: C1064.1 U21.13 | length 61.3
  Top w8: U21.13@3653.53,3310.74 3705.26,3310.74 C1064.1@3712,3304
N17950102: C171.1 R172.1 R173.2 | length 66
  Top w8: R172.1@3522,3172 R173.2@3522,3204 C171.1@3522,3238
N17950600: C176.1 R175.1 R176.2 | length 68
  Top w8: R175.1@3832,3188 R176.2@3832,3220 C176.1@3832,3256
N17950647: C176.2 U639.2 | length 54.3
  Top w8: C176.2@3832,3292 3832.16,3291.84 U639.2@3886.26,3291.84
N17950655: C182.2 R164.2 U639.6 | length 81.6
  Top w8: U639.6@3924.16,3234.26 3924,3234.11 3924,3214 3926,3212
  Top w20: 3926,3212 3926,3197.76 3932,3191.76 C182.2@3932,3188 R164.2@3964,3188
N17950661: C179.1 U639.13 | length 89.6
  Top w8: U639.13@3963.53,3329.74 3963.53,3335.15 3972.38,3344 C179.1@4044,3344
N17951357: CA21.2 CA81.2 LA11.2 | length 178.8
  Top w8: CA81.2@3910,3038 LA11.2@3910,3072 3936,3098 CA21.2@4044,3098
N17955795: C1053.2 U630.1 | length 42.6
  Top w8: C1053.2@2139.5,2974 2139.59,2974.09 U630.1@2182.09,2974.09
N20207161: R953.1 U1.E4 | length 336.8
  Top w5: v2(2188,2252.32) 2190.28,2254.6 2203.76,2254.6 U1.E4@2204.4,2254.36
  Bottom w5: R953.1@1916.73,2368.27 1934,2368 1958,2344 2094,2344 2183,2255 2183,2254.6 2185.72,2254.6 v2(2188,2252.32)
N20207869: R952.1 U1.D5 | length 364.4
  Top w5: v2(2223.2,2254.2) 2238.95,2254.2 U1.D5@2240.6,2254.36
  Bottom w5: R952.1@1941.73,2389.27 1941.73,2373 1961.73,2353 2100,2353 2183,2270 2207.4,2270 v2(2223.2,2254.2)
N20386056: CA66.2 UA4.27 | length 153
  Top w4: UA4.27@3766,2597.3 UA4.27@3767.5,2598.8
  Top w5: CA66.2@3751,2464 3740.71,2474.29 3740.71,2530.5 3766,2555.79 3766,2572.99 3766,2586.2 3768,2588.2 3768,2598.8 UA4.27@3767.5,2598.8
N20386057: CA65.2 UA4.26 | length 155.7
  Top w4: UA4.26@3751.76,2598.8 UA4.26@3754,2596.56
  Top w5: CA65.2@3719,2464 3717.94,2464 3717.94,2465.06 3729.71,2476.83 3729.71,2535.06 3755,2560.35 3755,2585.69 3751.76,2588.93 UA4.26@3751.76,2598.8
N20386082: UA4.8 UA5.3 | length 123.2
  Top w5: UA5.3@3510.31,2821.5 3510.31,2816.22 3521.03,2805.5 UA4.8@3623.8,2805.5
N20386085: LA16.1 UA4.40 | length 93.9
  Top w10: UA4.40@3974.2,2648.02 3997.98,2648.02 4009,2637
  Top w20: 4009,2637 4034.52,2611.48 LA16.1@4053,2611.48
N21240349: C107.2 L12.1 L13.2 | length 69.2
  Top w8: L13.2@2028.5,2407.5 2028.5,2440.5 C107.2@2030.5,2442.5 2031.5,2443.5 L12.1@2063.5,2443.5
N21250933: C82.2 L5.1 L14.2 | length 110.9
  Top w8: L5.1@2340.23,2413.23 2380.77,2453.77 C82.2@2401.23,2453.77 2401.77,2453.77 L14.2@2424.77,2476.77
N21361448: R903.1 U1.R12 | length 2017.2
  Top w5: R903.1@362,1675 394.25,1642.75 676.18,1642.75 713.93,1605 1910,1605 2079.49,1774.49 v1(2079.49,1792.72) ; v2(2151.5,1928.5) U1.R12@2168.21,1928.64
  Bottom w5: v1(2079.49,1792.72) 2079.49,1856.49 v2(2151.5,1928.5)
N21361450: R906.1 U1.P12 | length 2330.3
  Top w5: v1(261,1404) 276,1419 276,1539.5 295.5,1559 776.81,1559 812.81,1595 1915,1595 2101.59,1781.59 v1(2101.59,1802.6) ; U1.P12@2186.31,1946.74 2186.57,1947 v2(2202.5,1947)
  Bottom w4: 2169.5,1930 2187.5,1948 2201.5,1948 v2(2202.5,1947)
  Bottom w5: v1(261,1404) R906.1@261,1433 ; v1(2101.59,1802.6) 2101.59,1854.75 2169.5,1922.66 2169.5,1930
N21361482: R904.1 U1.U13 | length 2021.5
  Top w5: R904.1@362,1433 371,1424 684,1424 843.59,1583.59 1918.59,1583.59 2118.24,1783.24 2118.24,1809.86 2109,1819.1 2109,1831.41 2151.03,1873.44 U1.U13@2150.12,1874.36
N21361518: R902.1 U1.R13 | length 2095.3
  Top w5: v1(469,1674) 734,1674 767.06,1640.94 1893.07,1640.94 2125.33,1873.21 2130.36,1873.21 2167.7,1910.55 U1.R13@2186.31,1910.55
  Bottom w5: R902.1@462,1434 463,1433 464.74,1432.28 476,1443.53 476,1667 v1(469,1674)
N21373249: R907.2 R908.2 U1.D6 | length 6831.8
  Top w5: U1.D6@2258.69,2236.26 2258.69,2254.65 v2(2276.61,2272.58)
  Inner Layer 3 w5: v2(2276.61,2272.58) 2294.69,2254.5 2359.5,2254.5 2399,2294 3084,2294 3165,2375 3165,2944.18 3087.18,3022 2964.73,3022 2944,3042.73 2944,3288 2962,3306 2962,3320 v1(2944,3338)
  Bottom w5: R908.2@595,1387 596,1388 R907.2@596,1421 584,1433 584,1639 640,1695 640,2440 678,2478 678,3313 1144,3779 1553,3779 1590,3742 2692,3742 2830,3604 2830,3454 2887,3397 2887,3395 v1(2944,3338)
N179502195: C1065.2 U21.8 | length 64.8
  Top w8: U21.8@3653.53,3215.26 3668.79,3200 C1065.2@3712,3200
N179507645: C1066.2 U639.8 | length 57.8
  Top w8: U639.8@3963.53,3234.26 3995.79,3202 C1066.2@4008,3202
N179512821: CA79.2 CA80.1 | length 32
  Top w8: CA79.2@3748,3236 CA80.1@3748,3268
N179513811: CA46.2 CA82.1 | length 34
  Top w8: CA46.2@4044,3238 CA82.1@4044,3272
O_N: C89.1 L624.2 | length 34.2
  Top w8: L624.2@2351.55,2499.62 2351.55,2500.33 C89.1@2375.21,2523.99
O_N_1: C102.1 L626.2 | length 34
  Top w8: L626.2@2111.5,2507.5 C102.1@2111.5,2541.5
O_P: C84.1 L623.2 | length 33.2
  Top w8: L623.2@2329.23,2524.37 2329.23,2527.51 C84.1@2350.46,2548.74
O_P_1: C95.1 L625.2 | length 34
  Top w8: L625.2@2147.5,2507.5 C95.1@2147.5,2541.5
OSC_O: C108.1 R108.2 U11.1 U33.1 | length 388
  Top w5: R108.2@2697,2483 2704.5,2490.5 2730,2490.5 C108.1@2730,2483 2737,2490 2950,2490 U11.1@2951.69,2488.31 ; U11.1@2951.69,2499.5 U11.1@2951.69,2488.31 ; U33.1@2991,2412.94 2979.44,2424.5 2976.5,2424.5 2976.5,2478.5 U11.1@2951.69,2478.5 U11.1@2951.69,2488.31
P1: C113.1 C123.1 R109.1 R110.2 R111.2 R112.1 R113.2 R114.2 R115.1 R116.2 R117.2 R118.1 R119.2 R120.2 R121.1 R122.2 R123.2 | length 3368.3
  Top w20: v1(655,715) 659.12,719.12 C113.1@659.12,769 ; v1(845,750) 870,750 R120.2@881,761 881,764 R118.1@854,791 ; R119.2@1101,753 1130,753 v1(1130,750) ; R115.1@1359,791 1359,750 v1(1360,750) ; v1(1425,750) 1425,751 R117.2@1449,751 ; v1(1625,750) 1626,749 R116.2@1651,749 ; R112.1@1864,791 1864,769 1880,753 v1@1975,753 ; v1(1975,750) v1@1975,753 ; R114.2@2001,753 v1@1975,753 ; v1(2170,750) 2170,753 R113.2@2199,753 ; R109.1@2364,791 2364,761 v1@2374,751 ; v1(2375,750) v1@2374,751 ; v1(2575,750) 2575,751 R111.2@2549,751 v1@2374,751 ; R110.2@2751,751 2775,751 v1(2775,750) ; v1(3065,755) R121.1@3065,787 ; v1(3175,755) R122.2@3201,755 ; v1(3325,755) 3327,757 R123.2@3354,757 3408.88,757 C123.1@3408.88,754
  Bottom w20: v1(655,715) 690,750 v1(845,750) v1(1130,750) v1(1360,750) v1(1425,750) v1(1625,750) v1(1975,750) v1(2170,750) v1(2375,750) ; v1(2575,750) v1(2775,750) 3060,750 v1(3065,755) v1(3175,755) v1(3325,755)
PA0_OUT+: C84.2 C85.1 C86.2 L6.1 | length 100.5
  Top w8: C84.2@2375.92,2574.2 2375.92,2575.37 C86.2@2398.77,2598.23 2398.77,2601.31 2441.94,2644.48 C85.1@2444.77,2644.48
PA0_OUT-: C86.1 C89.2 C90.1 L8.1 | length 104.6
  Top w8: C89.2@2400.67,2549.45 2400.91,2549.45 C86.1@2424.23,2572.77 2424.23,2574.44 C90.1@2443.79,2594 ; C90.1@2444.77,2599.23 2443.79,2598.24 C90.1@2443.79,2594 ; L8.1@2469.52,2619.73 C90.1@2443.79,2594
PA0_OUT_1: C85.2 C87.1 L7.1 L8.2 | length 106.6
  Top w8: C85.2@2470.23,2669.94 2494.39,2669.94 2494.98,2670.52 ; L8.2@2494.98,2645.19 2494.98,2670.52 ; L7.1@2520.27,2716.27 2520.27,2699 2506.73,2685.46 C87.1@2506.73,2682.27 2494.98,2670.52
PA1_OUT+: C95.2 C96.1 C101.2 L9.1 | length 96
  Top w8: C95.2@2147.5,2577.5 C101.2@2147.5,2609.5 L9.1@2147.5,2641.5 C96.1@2147.5,2673.5
PA1_OUT-: C101.1 C102.2 C105.1 L11.1 | length 96
  Top w8: C102.2@2111.5,2577.5 C101.1@2111.5,2609.5 C105.1@2111.5,2641.5 L11.1@2111.5,2673.5
PA1_OUT_1: C96.2 C99.1 L10.1 L11.2 | length 106
  Top w8: L11.2@2111.5,2709.5 2129.5,2727.5 ; L10.1@2143,2775.5 2140.5,2775.5 2138,2773 2138,2749 C99.1@2132,2743 2129.5,2740.5 2129.5,2727.5 ; C96.2@2147.5,2709.5 2129.5,2727.5
PA_PE_G0: R932.1 U1.E5 | length 688.3
  Top w5: v1(1732.25,2551.78) 1780,2551.78 R932.1@1780,2552 ; v2(2206,2236) 2206.26,2236.26 U1.E5@2222.5,2236.26
  Bottom w5: v1(1732.25,2551.78) 1732.25,2520.75 1919,2334 2087.51,2334 2173.45,2248.06 2173.45,2246.36 2182.52,2237.29 2204.71,2237.29 v2(2206,2236)
PA_PE_G1: TP605.1 U1.E6 | length 56.2
  Top w5: v2(2217,2218) 2217.17,2218.17 U1.E6@2240.6,2218.17
  Bottom w5: TP605.1@2185.39,2220.26 2214.74,2220.26 v2(2217,2218)
PCIE_REXT: R381.1 U1.C10 | length 93.9
  Top w5: U1.C10@2349.17,2181.98 v2(2367.36,2181.98)
  Bottom w5: v2(2367.36,2181.98) 2384.39,2199 R381.1@2436,2199
PCIE_RST#: RA9.2 U1.D10 | length 1262.9
  Top w5: v2(2330.95,2147.24) 2331.01,2147.24 2331.01,2163.88 U1.D10@2331.07,2163.88 ; v1(3185,2325) 3223.69,2325 3400,2501.31 RA9.2@3400,2512
  Bottom w5: v2(2330.95,2147.24) 2330.95,2180.95 2455,2305 3165,2305 v1(3185,2325)
PCIE_RXN: CA65.1 U1.B9 | length 1592.3
  Top w5: U1.B9@2349.17,2218.17 2349.17,2235.71 2473.46,2360 2775,2360 2865,2270 3632.1,2270 3730,2367.9 3730,2417 CA65.1@3719,2428
PCIE_RXP: CA66.1 U1.A9 | length 1570.5
  Top w5: U1.A9@2367.26,2236.26 2367.26,2239 2478.26,2350 2770.86,2350 2860.86,2260 3636.24,2260 3740,2363.76 3740,2411.41 3751,2422.41 CA66.1@3751,2428
PCIE_TX_N: C81.2 UA4.29 | length 1527.7
  Top w5: C81.2@2604.5,2318.5 2604.5,2319.5 2605.5,2319.5 2618.54,2306.46 2770,2306.46 2851.46,2225 3656.86,2225 3802,2370.14 3802,2579.52 3799,2582.52 UA4.29@3799,2598.8
PCIE_TX_P: C80.2 UA4.30 | length 1544.1
  Top w5: C80.2@2603,2285 2614.39,2296.46 2765.86,2296.46 2847.32,2215 3661,2215 3812,2366 3812,2579.78 3814.75,2582.52 UA4.30@3814.75,2598.8
PCIE_TXN: C81.1 U1.A10 | length 237.8
  Top w5: U1.A10@2385.36,2218.17 2389.31,2218.17 2398.7,2227.56 2398.7,2249.96 2458.74,2310 2560,2310 C81.1@2568.5,2318.5
PCIE_TXP: C80.1 U1.B10 | length 261.9
  Top w5: U1.B10@2367.26,2200.07 2385.36,2200.07 2408.7,2223.41 2408.7,2245.82 2462.88,2300 2550,2300 2566,2284 2567,2284 C80.1@2567,2285
PERST_N: CA50.1 RA9.1 RA13.2 UA4.18 | length 284.7
  Top w5: RA9.1@3400,2548 RA13.2@3400,2580 3400.5,2580 3400.5,2579.5 3445,2624 3551,2624 CA50.1@3569,2642 3575.02,2648.02 UA4.18@3623.8,2648.02
PLL_VC_CAP: C94.1 U1.B4 | length 98.4
  Top w5: U1.B4@2258.69,2308.64 v2(2258.7,2325)
  Bottom w8: v2(2258.7,2325) 2280,2325 2322.27,2367.27 C94.1@2322.27,2368.27
POWERLED: D7.1 R158.1 | length 50.1
  Top w4: R158.1@674,3577 674,3622.78 D7.1@678.33,3622.78
PWRLED: D7.2 R159.2 | length 49.3
  Top w4: D7.2@729.51,3622.78 733,3622.78 R159.2@733,3577
REF_CLK0_OUT: R908.1 R911.1 | length 35
  Bottom w5: R911.1@560,1351 R908.1@595,1351
REFCLK0_OUT: C976.1 JP2.8 R911.2 | length 152.4
  Bottom w5: JP2.8@526,1504 526,1388 C976.1@525,1387 R911.2@560,1387
RF0_2G_RX_1: C998.1 U1.A3 | length 71.1
  Top w8: U1.A3@2258.69,2344.83 2258.93,2345.07 2259.07,2345.07 2260,2346 v2(2275,2346)
  Bottom w8: v2(2275,2346) 2299,2370 2299,2390.04 C998.1@2298.77,2390.27
RF0_2G_TR: C971.1 C1050.1 C1052.1 L601.2 R921.2 | length 181
  Top w8: C1050.1@2725,2846 2758,2846 R921.2@2758,2844 2870,2844 C971.1@2870,2847 L601.2@2901,2847
RF0_LNA_IN: C1000.1 C1002.2 L640.2 Q2.1 | length 125.8
  Bottom w8: Q2.1@2354.5,2705.59 2361,2712.09 2405.09,2712.09 L640.2@2409,2716 C1000.1@2442.5,2716 C1002.2@2476,2716
RF0_PA2: L5.2 U1.A2 | length 84.5
  Top w8: U1.A2@2240.6,2362.93 2245.52,2367.85 2285.85,2367.85 2305.77,2387.77 L5.2@2314.77,2387.77
RF0_PA_OUTN: C842.1 L624.1 U1.B2 | length 185.1
  Top w4: U1.B2@2222.5,2344.83 2222.5,2362.9 2251.1,2391.5
  Top w8: 2251.1,2391.5 2276.54,2416.94 C842.1@2284.49,2416.94 2284.49,2446.49 2312.17,2474.17 L624.1@2326.09,2474.17
RF0_PA_OUTP: C841.1 L623.1 U1.A1 | length 171.2
  Top w8: U1.A1@2222.5,2381.02 2222.5,2384.5 2246.74,2408.74 2246.74,2452.8 C841.1@2244.27,2455.27 2245.39,2456.39 2275.39,2456.39 2303.77,2484.77 L623.1@2303.77,2498.91
RF1_2G_RX_1: C983.1 U1.C1 | length 51.9
  Top w8: v2(2175,2357) 2175,2356.14 U1.C1@2186.31,2344.83
  Bottom w8: C983.1@2150.23,2381.77 v2(2175,2357)
RF1_2G_TR: C973.1 C1047.1 C1049.1 L600.2 R919.2 | length 264
  Top w8: C1047.1@2336,2915.5 R919.2@2369.5,2915.5 C1049.1@2369.48,2915.62 2367,2918.1 C973.1@2367,3113 L600.2@2367,3145
RF1_LNA_IN: C984.2 C985.1 L639.2 Q1.1 | length 121.9
  Bottom w8: Q1.1@2049,2732.59 2057.41,2741 2057.41,2774 2063.5,2774 2064.5,2775 L639.2@2062,2777.5 C985.1@2062,2810.5 C984.2@2062,2843.5
RF1_PA2: L12.2 U1.E2 | length 174.7
  Top w8: L12.2@2063.5,2407.5 2063.5,2397.06 2090,2370.56 2090,2345 2145,2290 2167.67,2290 U1.E2@2168.21,2290.55
RF1_PA_OUTN: C844.1 L626.1 U1.E1 | length 197.4
  Top w8: L626.1@2111.5,2471.5 2124,2459 2124,2419 2110,2405 2106,2405 C844.1@2104.5,2403.5 2123,2385 2123,2344.12 2150.12,2317 U1.E1@2150.12,2308.64
RF1_PA_OUTP: C843.1 L625.1 U1.D1 | length 188.7
  Top w8: L625.1@2147.5,2471.5 2137,2461 2137,2418 2154.25,2401.19 C843.1@2155.47,2400 ; C843.1@2156.5,2403.5 C843.1@2156.5,2400 ; U1.D1@2168.21,2326.74 2162,2326.74 2138,2350.74 2138,2385 2153,2400 C843.1@2155.47,2400 ; C843.1@2155.47,2400 C843.1@2156.5,2400 ; C843.1@2155.47,2400 2156.5,2399 C843.1@2156.5,2400
RF_5G_A: CA31.1 CA32.1 CA33.1 R869.1 U638.4 | length 153
  Top w8: R869.1@4170,3310 U638.4@4200.23,3310 CA32.1@4250,3310 ; CA32.1@4250,3307 CA32.1@4250,3310 ; CA33.1@4284,3276 CA31.1@4284,3310 4284,3311 CA32.1@4250,3311 CA32.1@4250,3310
RF_XI: C1062.2 R810.2 U1.A5 U11.3 U33.2 | length 1103.6
  Top w5: U1.A5@2294.88,2308.64 2326.37,2308.64 2458.72,2441 2459.39,2441 2460.39,2442 2544,2442 2602,2500 2910,2500 2920,2510 3007.08,2510 3036.5,2539.42 U11.3@3036.5,2541.5 ; U11.3@3038.31,2541.5 U11.3@3036.5,2541.5 ; R810.2@3113.5,2519 3114.5,2520 C1062.2@3114.5,2552 3061.44,2605.06 U33.2@2991,2605.06 2994,2602.06 2994,2581.87 3034.37,2541.5 U11.3@3036.5,2541.5
RF_XO: R108.1 U1.A6 | length 449
  Top w5: U1.A6@2312.98,2290.55 2321,2290.55 2462.45,2432 2547,2432 2606,2491 2661,2491 R108.1@2661,2483 R108.1@2654,2490
RFOUT_G0: C88.1 C1055.2 C1060.1 L7.2 | length 78.8
  Top w8: C88.1@2569.23,2717.73 2545.73,2741.23 L7.2@2545.73,2741.73 2549.23,2738.73 2549.73,2738.73 C1060.1@2578,2767
RFOUT_G1: C100.1 C1054.2 C1059.1 L10.2 | length 73.6
  Top w8: L10.2@2179,2775.5 C100.1@2179,2809 2179,2844 2182,2844 C1059.1@2183.5,2842.5
RST_N: CA39.1 RA7.1 RA13.1 UA4.15 | length 295.3
  Top w5: RA13.1@3400,2616 3400,2650.75 3415.23,2665.98 3461.19,2665.98 RA7.1@3478.69,2648.48 3478.69,2654.95 3485,2654.95 3490.05,2660 3551,2660 CA39.1@3569,2678 3586.26,2695.26 UA4.15@3623.8,2695.26
RST_PBC: R355.2 S3.1 U1.P11 | length 2393.1
  Top w5: S3.1@180,1258.58 200.58,1238 R355.2@365,1238 365,1255 465,1355 712,1355 811,1454 v1(822,1454) ; v2(2168,1948.5) 2168,1964.62 U1.P11@2168.21,1964.83
  Bottom w4: 2138.2,1935 2151.7,1948.5 v2(2168,1948.5)
  Bottom w5: v1(822,1454) 831,1445 1765,1445 2039.61,1719.61 2039.61,1836.41 2138.2,1935
RXIM0: U1.T15 U14.9 | length 1926.6
  Top w5: U14.9@759,1199 720,1199 714.5,1204.5 714.5,1226.72 969.44,1481.66 2012.16,1481.66 2189.5,1659 2189.5,1824 2189.69,1824 2204.4,1838.72 U1.T15@2204.4,1856.26
RXIM1: U1.R17 U14.1 | length 1316.7
  Top w5: U14.1@1559,1199 1520,1199 1514.5,1204.5 1514.5,1256.72 1600.78,1343 2080.78,1343 2315.21,1577.43 2315.21,1781.65 U1.R17@2258.69,1838.17
RXIM2: U1.P17 U12.9 | length 1192.5
  Top w5: U12.9@1764,1199 1725,1199 1719.5,1204.5 1719.5,1241.72 1774.23,1296.45 2099.23,1296.45 2361.25,1558.47 2361.25,1774.53 2278.15,1857.63 U1.P17@2276.79,1856.26
RXIM3: U1.M14 U12.2 | length 902.9
  Top w5: U1.M14@2258.69,1946.74 2268.1,1946.74 2268.19,1946.83 v2(2276.18,1946.83)
  Bottom w5: v2(2276.18,1946.83) 2276.18,1915.92 2294.19,1897.91 2294.19,1825.98 2304,1816.17 2350.23,1769.93 2350.23,1432.27 2508.5,1274 2508.5,1204.5 2503,1199 U12.2@2464,1199
RXIM4: U1.N17 U16.5 | length 1089.7
  Top w5: U1.N17@2294.88,1874.36 2295.65,1875.13 2407.37,1763.41 2407.37,1573.41 2684.66,1296.12 2854.66,1296.12 2874.5,1276.28 2874.5,1239.09 2919.59,1194 U16.5@2969,1194
RXIP0: U1.U15 U14.10 | length 1905.5
  Top w5: U14.10@659,1199 698,1199 703.5,1204.5 703.5,1231.28 964.88,1492.66 2007.6,1492.66 2178.5,1663.56 2178.5,1830.36 U1.U15@2186.31,1838.17
RXIP1: U1.R16 U14.2 | length 1339.3
  Top w5: U14.2@1459,1199 1498,1199 1503.5,1204.5 1503.5,1261.28 1596.22,1354 2076.22,1354 2304.21,1581.99 2304.21,1777.09 2261.61,1819.69 2258.86,1819.69 2240.6,1837.95 U1.R16@2240.6,1856.26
